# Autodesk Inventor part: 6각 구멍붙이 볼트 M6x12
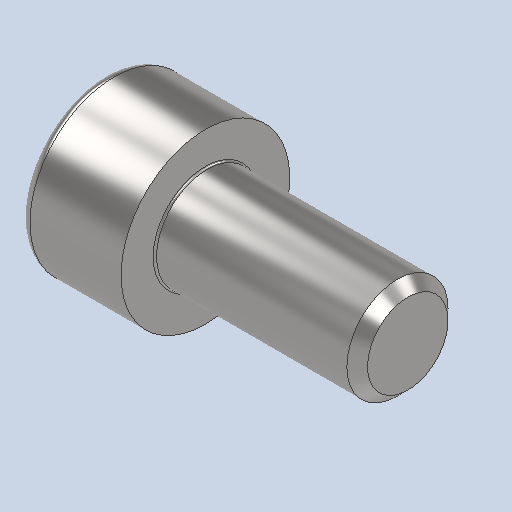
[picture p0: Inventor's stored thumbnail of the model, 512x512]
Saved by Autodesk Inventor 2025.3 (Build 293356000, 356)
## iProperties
Created: 2025-09
Part Number: 6각 구멍붙이 볼트 M6x12
Material: 강철, 연강
Description: 6각머리 태핑 나사
Document SubType Name: Modeling
Designer: PC-15
Density: 7.85 g/cm^3
Appearance: 기본값
Author: jhkim
Sending System: Autodesk Inventor 2026
Preprocessor: ST-DEVELOPER v20.1
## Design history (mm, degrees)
feature "Solid1"
node "솔리드1"
